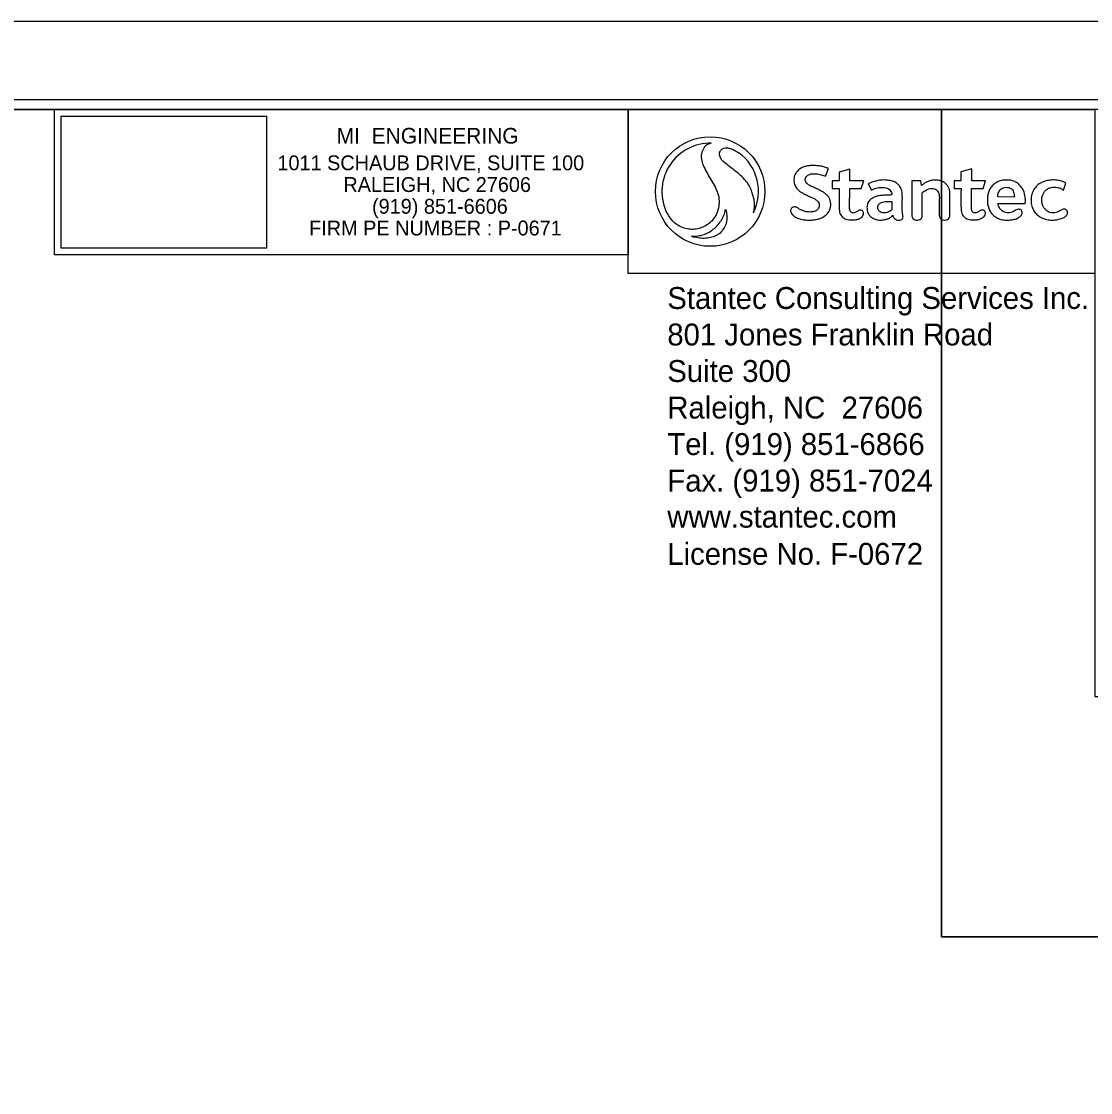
# Model space of a CAD drawing. Extents: x 2568837 to 2570520, y 536545 to 537640.
# Drawn here: x 2570028.8 to 2570302.1, y 537365.9 to 537639.6 of the extents above; entities that cross this region are included whole.
import ezdxf

# ---------------------------------------------------------------- set-up
doc = ezdxf.new("R2010")
doc.units = 0
for name, color, linetype in [('Old_Level_1', 7, 'Continuous'), ('Prop DSN Text', 7, 'Continuous'), ('Prop Grid Mask', 7, 'Continuous'), ('Scratch_Level_0', 7, 'Continuous'), ('Sheet Clip Boundary CELL', 7, 'Continuous'), ('Sheet Cutting Line CELL', 7, 'Continuous'), ('Sheet Data Text CELL', 7, 'Continuous'), ('Sheet Layout Plan Border', 7, 'Continuous'), ('Sheet North Arrow Point CELL', 7, 'Continuous'), ('Sheet Plan CELL', 7, 'Continuous'), ('Sheet Plan Layout CELL', 7, 'Continuous'), ('Sheet Plot Border Inside CELL', 7, 'Continuous'), ('Sheet Plot Border Outside CELL', 7, 'Continuous')]:
    doc.layers.add(name, color=color, linetype=linetype)

msp = doc.modelspace()

# ---------------------------------------------------------------- linework, layer by layer
at = {"layer": 'Old_Level_1'}
msp.add_lwpolyline([(2570037.18, 537617.15), (2570183.85, 537617.15), (2570183.85, 537579.97), (2570037.18, 537579.97)], close=True, dxfattribs=at)
at = {"layer": 'Prop DSN Text'}
msp.add_lwpolyline([(2570038.8, 537581.75), (2570091.47, 537581.75), (2570091.47, 537615.37), (2570038.8, 537615.37)], close=True, dxfattribs=at)
at = {"layer": 'Scratch_Level_0'}
msp.add_lwpolyline([(2570183.85, 537617.15), (2570303.14, 537617.16), (2570303.15, 537575.21), (2570183.85, 537575.19)], close=True, dxfattribs=at)
at = {"layer": 'Sheet Clip Boundary CELL'}
msp.add_lwpolyline([(2569053.18, 536567.15), (2570453.19, 536567.15), (2570453.19, 537405.66), (2570263.93, 537405.66), (2570263.93, 537617.15), (2569053.18, 537617.15)], close=True, dxfattribs=at)
at = {"layer": 'Sheet Cutting Line CELL'}
msp.add_line((2570520.19, 537639.64), (2568836.69, 537639.64), dxfattribs=at)
at = {"layer": 'Sheet Data Text CELL'}
for p, q in [((2570234.35, 537600.09), (2570235.04, 537602.04)), ((2570240.54, 537601.92), (2570237.78, 537601.15)), ((2570240.54, 537598.86), (2570240.54, 537601.92)), ((2570271.69, 537601.93), (2570268.93, 537601.16)), ((2570271.69, 537598.86), (2570271.69, 537601.93)), ((2570237.78, 537598.86), (2570236.03, 537598.86)), ((2570236.03, 537598.86), (2570236.03, 537596.94)), ((2570237.78, 537601.15), (2570237.78, 537598.86)), ((2570244.1, 537598.86), (2570240.54, 537598.86)), ((2570243.44, 537596.94), (2570244.1, 537598.86)), ((2570258.66, 537598.86), (2570256.34, 537598.86)), ((2570256.34, 537598.86), (2570256.35, 537590.06)), ((2570258.82, 537597.69), (2570258.66, 537598.86)), ((2570268.93, 537598.87), (2570267.18, 537598.87)), ((2570267.18, 537598.87), (2570267.18, 537596.95)), ((2570268.93, 537601.16), (2570268.93, 537598.87)), ((2570275.25, 537598.86), (2570271.69, 537598.86)), ((2570274.59, 537596.95), (2570275.25, 537598.86)), ((2570236.03, 537596.94), (2570237.8, 537596.94)), ((2570240.48, 537592.1), (2570240.52, 537596.94)), ((2570240.52, 537596.94), (2570243.44, 537596.94)), ((2570245.25, 537598.16), (2570246.09, 537596.54)), ((2570259.04, 537590.07), (2570259.04, 537595.87)), ((2570267.18, 537596.95), (2570268.95, 537596.95)), ((2570271.63, 537592.1), (2570271.67, 537596.95)), ((2570271.67, 537596.95), (2570274.59, 537596.95)), ((2570295.14, 537596.48), (2570295.75, 537598.28)), ((2570251.28, 537593.65), (2570251.28, 537591.48)), ((2570282.59, 537594.76), (2570278.39, 537594.77)), ((2570278.39, 537593.08), (2570285.38, 537593.08))]:
    msp.add_line(p, q, dxfattribs=at)
for points in [[(2570205.09, 537608.51), (2570205.09, 537608.51)], [(2570212.18, 537606.09), (2570212.18, 537606.09)]]:
    msp.add_lwpolyline(points, dxfattribs=at)
msp.add_circle((2570204.83, 537596.17), 14, dxfattribs=at)
for start, end in [(88.7738, 203.6916), (88.7673, 88.7738), (333.7886, 53.4398), (247.1256, 251.4651)]:
    msp.add_arc((2570204.83, 537596.17), 12.34, start, end, dxfattribs=at)
for points, degree in [([(2570205.09, 537608.51), (2570204.79, 537608.45), (2570204.09, 537608.3), (2570203.17, 537607.37), (2570202.49, 537605.83), (2570202.58, 537604.11), (2570203.19, 537602.44), (2570204.11, 537600.83), (2570205.07, 537599.04), (2570206.12, 537597.35), (2570206.86, 537595.64), (2570207.2, 537593.78), (2570206.98, 537591.91), (2570206.43, 537590.2), (2570205.38, 537588.64), (2570204, 537587.54), (2570202.55, 537586.89), (2570201.24, 537586.48), (2570199.78, 537586.48), (2570198.16, 537586.71), (2570196.55, 537587.44), (2570194.84, 537588.89), (2570194.03, 537590.31), (2570193.52, 537591.21)], 3), ([(2570205.09, 537608.51), (2570205.09, 537608.51), (2570205.09, 537608.51), (2570205.09, 537608.51)], 2), ([(2570215.9, 537590.72), (2570216.01, 537591.15), (2570216.19, 537591.97), (2570216.16, 537593.27), (2570216.03, 537594.42), (2570215.69, 537595.48), (2570215.3, 537596.71), (2570214.6, 537598.05), (2570213.6, 537599.31), (2570212.31, 537600.63), (2570210.68, 537601.81), (2570209.01, 537603.18), (2570207.67, 537604.18), (2570207.2, 537605.37), (2570207.19, 537606.27), (2570207.64, 537606.88), (2570208.23, 537607.3), (2570209.02, 537607.37), (2570209.95, 537607.19), (2570211.03, 537606.74), (2570211.78, 537606.32), (2570212.18, 537606.09)], 3), ([(2570235.04, 537602.04), (2570234.91, 537602.1), (2570234.37, 537602.36), (2570233.33, 537602.63), (2570232.06, 537602.79), (2570230.9, 537602.85), (2570229.93, 537602.75), (2570229.01, 537602.56), (2570228.12, 537602.21), (2570227.26, 537601.62), (2570226.64, 537600.83), (2570226.29, 537600.03), (2570226.21, 537599.29), (2570226.25, 537598.6), (2570226.39, 537597.95), (2570226.67, 537597.41), (2570227.01, 537596.92), (2570227.42, 537596.48), (2570227.93, 537596.08), (2570228.55, 537595.7), (2570229.31, 537595.31), (2570230.16, 537594.92), (2570231.03, 537594.55), (2570231.74, 537594.18), (2570232.27, 537593.74), (2570232.63, 537593.32), (2570232.75, 537592.8), (2570232.74, 537592.32), (2570232.54, 537591.78), (2570232.09, 537591.33), (2570231.38, 537591.03), (2570230.54, 537590.91), (2570229.61, 537590.95), (2570228.79, 537591.12), (2570228.13, 537591.45), (2570227.59, 537591.67), (2570227.22, 537592.01), (2570226.88, 537592.14), (2570226.56, 537592.28), (2570226.22, 537592.25), (2570225.88, 537592.15), (2570225.59, 537591.9), (2570225.4, 537591.54), (2570225.39, 537591.15), (2570225.45, 537590.76), (2570225.75, 537590.35), (2570226.34, 537589.77), (2570227.38, 537589.26), (2570228.66, 537588.92), (2570229.96, 537588.85), (2570231.09, 537588.88), (2570232.06, 537589.01), (2570232.92, 537589.27), (2570233.82, 537589.67), (2570234.68, 537590.35), (2570235.35, 537591.19), (2570235.62, 537592.17), (2570235.66, 537593.07), (2570235.55, 537593.88), (2570235.24, 537594.52), (2570234.85, 537595.17), (2570234.18, 537595.72), (2570233.42, 537596.23), (2570232.58, 537596.63), (2570231.68, 537597.06), (2570230.73, 537597.46), (2570229.93, 537597.89), (2570229.39, 537598.37), (2570229.16, 537598.85), (2570229.12, 537599.35), (2570229.27, 537599.8), (2570229.57, 537600.2), (2570230, 537600.48), (2570230.57, 537600.69), (2570231.25, 537600.74), (2570231.92, 537600.71), (2570232.58, 537600.61), (2570233.22, 537600.47), (2570233.83, 537600.29), (2570234.19, 537600.15), (2570234.35, 537600.09)], 3), ([(2570251.54, 537590.11), (2570251.55, 537590.02), (2570251.57, 537589.79), (2570251.8, 537589.46), (2570252.12, 537589.08), (2570252.71, 537588.81), (2570253.33, 537588.83), (2570253.9, 537588.96), (2570254.13, 537589.41), (2570254.14, 537589.87), (2570254.01, 537590.48), (2570253.86, 537592.17), (2570253.97, 537593.95), (2570253.94, 537595.87), (2570253.72, 537596.81), (2570253.19, 537597.65), (2570252.63, 537598.29), (2570251.7, 537598.76), (2570250.55, 537599.06), (2570249.18, 537599.15), (2570247.8, 537599.01), (2570246.46, 537598.7), (2570245.64, 537598.34), (2570245.25, 537598.16)], 3), ([(2570259.04, 537595.87), (2570259.09, 537595.91), (2570259.28, 537596.08), (2570259.73, 537596.36), (2570260.31, 537596.74), (2570261.06, 537596.97), (2570261.81, 537596.96), (2570262.54, 537596.73), (2570263.04, 537596.21), (2570263.31, 537595.59), (2570263.45, 537594.75), (2570263.36, 537593.5), (2570263.43, 537591.91), (2570263.34, 537590.59), (2570263.4, 537589.68), (2570263.71, 537589.19), (2570264.26, 537588.84), (2570264.9, 537588.85), (2570265.51, 537589), (2570266.01, 537589.37), (2570266.15, 537590.1), (2570266.04, 537591.38), (2570266.11, 537592.95), (2570266.08, 537594.68), (2570266.14, 537595.77), (2570265.99, 537596.73), (2570265.69, 537597.4), (2570265.22, 537598.09), (2570264.45, 537598.62), (2570263.49, 537599.08), (2570262.39, 537599.11), (2570261.4, 537599.05), (2570260.51, 537598.76), (2570259.72, 537598.39), (2570259.19, 537597.97), (2570258.91, 537597.76), (2570258.82, 537597.69)], 3), ([(2570285.38, 537593.08), (2570285.39, 537593.34), (2570285.42, 537594.02), (2570285.3, 537595.09), (2570285.02, 537596.3), (2570284.44, 537597.23), (2570283.79, 537598.05), (2570282.95, 537598.62), (2570281.9, 537599.03), (2570280.71, 537599.11), (2570279.55, 537599.09), (2570278.44, 537598.74), (2570277.5, 537598.2), (2570276.67, 537597.42), (2570276.11, 537596.46), (2570275.8, 537595.42), (2570275.68, 537594.36), (2570275.66, 537593.22), (2570275.92, 537592.16), (2570276.34, 537591.12), (2570276.98, 537590.24), (2570277.95, 537589.54), (2570279.16, 537588.94), (2570280.57, 537588.86), (2570281.85, 537588.88), (2570282.94, 537589.11), (2570283.8, 537589.53), (2570284.43, 537590.07), (2570284.65, 537590.66), (2570284.55, 537591.14), (2570284.32, 537591.52), (2570283.94, 537591.62), (2570283.57, 537591.67), (2570283.14, 537591.54), (2570282.63, 537591.22), (2570282.05, 537590.87), (2570281.34, 537590.71), (2570280.68, 537590.69), (2570280.03, 537590.86), (2570279.49, 537591.23), (2570278.95, 537591.66), (2570278.64, 537592.25), (2570278.44, 537592.72), (2570278.4, 537592.99), (2570278.39, 537593.08)], 3), ([(2570295.75, 537598.28), (2570295.52, 537598.41), (2570294.95, 537598.74), (2570293.83, 537599.03), (2570292.43, 537599.17), (2570290.95, 537599), (2570289.54, 537598.54), (2570288.37, 537597.76), (2570287.52, 537596.7), (2570287, 537595.47), (2570286.81, 537594.1), (2570286.92, 537592.71), (2570287.39, 537591.47), (2570288.1, 537590.51), (2570289.07, 537589.68), (2570290.41, 537589.06), (2570291.97, 537588.81), (2570293.41, 537588.91), (2570294.6, 537589.22), (2570295.54, 537589.65), (2570296.15, 537590.24), (2570296.18, 537590.8), (2570296.13, 537591.22), (2570295.85, 537591.48), (2570295.56, 537591.65), (2570295.24, 537591.67), (2570294.81, 537591.6), (2570294.42, 537591.27), (2570293.87, 537591.03), (2570293.31, 537590.77), (2570292.51, 537590.71), (2570291.68, 537590.78), (2570290.87, 537591.22), (2570290.27, 537591.82), (2570289.79, 537592.55), (2570289.64, 537593.41), (2570289.52, 537594.26), (2570289.76, 537595.1), (2570290.08, 537595.86), (2570290.56, 537596.48), (2570291.2, 537596.93), (2570291.94, 537597.22), (2570292.8, 537597.29), (2570293.66, 537597.21), (2570294.48, 537596.95), (2570294.93, 537596.63), (2570295.14, 537596.48)], 3), ([(2570237.8, 537596.94), (2570237.79, 537595.23), (2570237.78, 537593.42), (2570237.8, 537591.41), (2570237.89, 537590.92), (2570238.09, 537590.26), (2570238.46, 537589.82), (2570238.84, 537589.46), (2570239.24, 537589.2), (2570239.88, 537588.97), (2570240.76, 537588.88), (2570241.67, 537588.92), (2570242.58, 537589.04), (2570243.27, 537589.39), (2570243.78, 537589.81), (2570244.02, 537590.28), (2570244.04, 537590.69), (2570243.97, 537591.04), (2570243.79, 537591.24), (2570243.57, 537591.37), (2570243.31, 537591.42), (2570243.04, 537591.43), (2570242.76, 537591.36), (2570242.51, 537591.16), (2570242.24, 537590.95), (2570241.89, 537590.8), (2570241.53, 537590.68), (2570241.16, 537590.73), (2570240.83, 537590.9), (2570240.58, 537591.16), (2570240.47, 537591.59), (2570240.48, 537591.9), (2570240.48, 537592.1)], 3), ([(2570246.09, 537596.54), (2570246.22, 537596.6), (2570246.6, 537596.81), (2570247.23, 537597), (2570247.98, 537597.19), (2570248.69, 537597.24), (2570249.43, 537597.21), (2570250.1, 537597.01), (2570250.68, 537596.67), (2570251.09, 537596.18), (2570251.27, 537595.69), (2570251.27, 537595.38), (2570251.27, 537595.28)], 3), ([(2570268.95, 537596.95), (2570268.94, 537595.23), (2570268.93, 537593.43), (2570268.95, 537591.41), (2570269.04, 537590.93), (2570269.24, 537590.27), (2570269.61, 537589.82), (2570269.99, 537589.47), (2570270.39, 537589.2), (2570271.03, 537588.98), (2570271.91, 537588.88), (2570272.82, 537588.92), (2570273.73, 537589.05), (2570274.42, 537589.4), (2570274.93, 537589.81), (2570275.17, 537590.28), (2570275.19, 537590.69), (2570275.12, 537591.04), (2570274.94, 537591.25), (2570274.72, 537591.38), (2570274.46, 537591.42), (2570274.19, 537591.43), (2570273.91, 537591.36), (2570273.66, 537591.16), (2570273.39, 537590.95), (2570273.04, 537590.8), (2570272.68, 537590.69), (2570272.31, 537590.73), (2570271.98, 537590.91), (2570271.73, 537591.16), (2570271.62, 537591.59), (2570271.63, 537591.9), (2570271.63, 537592.1)], 3), ([(2570278.39, 537594.77), (2570278.39, 537594.85), (2570278.39, 537595.07), (2570278.41, 537595.48), (2570278.55, 537596), (2570278.88, 537596.56), (2570279.39, 537597.01), (2570280.08, 537597.25), (2570280.83, 537597.27), (2570281.53, 537597.06), (2570282.12, 537596.68), (2570282.41, 537596.03), (2570282.56, 537595.39), (2570282.58, 537594.96), (2570282.59, 537594.76)], 3), ([(2570251.27, 537595.28), (2570251.09, 537595.27), (2570250.51, 537595.26), (2570249.51, 537595.21), (2570248.33, 537595.15), (2570247.21, 537594.91), (2570246.19, 537594.48), (2570245.29, 537593.71), (2570244.87, 537592.62), (2570244.93, 537591.6), (2570245.09, 537590.71), (2570245.63, 537589.97), (2570246.41, 537589.29), (2570247.52, 537588.88), (2570248.67, 537588.86), (2570249.74, 537589), (2570250.55, 537589.28), (2570251.15, 537589.7), (2570251.4, 537589.96), (2570251.54, 537590.11)], 3), ([(2570251.28, 537591.48), (2570251.21, 537591.42), (2570250.95, 537591.23), (2570250.48, 537590.97), (2570249.83, 537590.71), (2570249.14, 537590.66), (2570248.54, 537590.82), (2570248.11, 537591.09), (2570247.84, 537591.41), (2570247.66, 537591.8), (2570247.63, 537592.21), (2570247.71, 537592.63), (2570247.96, 537593.02), (2570248.38, 537593.27), (2570248.89, 537593.5), (2570249.55, 537593.59), (2570250.23, 537593.62), (2570250.83, 537593.66), (2570251.15, 537593.66), (2570251.28, 537593.65)], 3), ([(2570200.03, 537584.8), (2570200.33, 537584.77), (2570201.04, 537584.7), (2570202.27, 537584.94), (2570203.63, 537585.26), (2570204.86, 537585.97), (2570206, 537586.77), (2570207.06, 537587.91), (2570207.94, 537589.18), (2570208.5, 537590.5), (2570208.67, 537591.28), (2570208.75, 537591.66)], 3), ([(2570208.75, 537591.66), (2570208.84, 537591.34), (2570209.07, 537590.54), (2570209.13, 537589.2), (2570208.9, 537587.75), (2570208.15, 537586.43), (2570207.14, 537585.21), (2570205.68, 537584.54), (2570204.12, 537584.19), (2570202.52, 537584.16), (2570201.42, 537584.37), (2570200.9, 537584.47)], 3), ([(2570256.35, 537590.06), (2570256.37, 537589.95), (2570256.43, 537589.69), (2570256.62, 537589.24), (2570257.11, 537588.87), (2570257.8, 537588.86), (2570258.49, 537588.91), (2570258.9, 537589.37), (2570259.05, 537589.76), (2570259.05, 537589.97), (2570259.04, 537590.07)], 3)]:
    msp.add_open_spline(points, degree=degree, dxfattribs=at)
at = {"layer": 'Sheet Layout Plan Border'}
msp.add_lwpolyline([(2569053.18, 536567.15), (2570453.19, 536567.15), (2570453.19, 537405.66), (2570263.93, 537405.66), (2570263.93, 537617.15), (2569053.18, 537617.15)], close=True, dxfattribs=at)
at = {"layer": 'Sheet North Arrow Point CELL'}
msp.add_line((2570235.07, 537544.21), (2570235.07, 537544.21), dxfattribs=at)
at = {"layer": 'Sheet Plan CELL'}
for points in [[(2569003.18, 536567.15), (2569003.15, 537617.13), (2570303.14, 537617.16), (2570303.15, 537467.1), (2570503.19, 537467.09), (2570503.19, 536567.15)], [(2570503.22, 537617.15), (2569003.18, 537617.15), (2569003.18, 536567.15), (2570503.19, 536567.15)]]:
    msp.add_lwpolyline(points, close=True, dxfattribs=at)
at = {"layer": 'Sheet Plan Layout CELL'}
for points in [[(2569003.15, 537617.13), (2569003.18, 536567.15), (2570503.18, 536567.15), (2570503.18, 537405.66), (2570263.93, 537405.66), (2570263.93, 537617.15)], [(2570263.93, 537405.66), (2570503.2, 537405.66), (2570503.23, 537617.15), (2570263.93, 537617.15)]]:
    msp.add_lwpolyline(points, close=True, dxfattribs=at)
at = {"layer": 'Sheet Plot Border Inside CELL'}
msp.add_lwpolyline([(2568849.69, 536564.64), (2570515.68, 536564.65), (2570515.69, 537619.64), (2568849.69, 537619.64)], close=True, dxfattribs=at)
at = {"layer": 'Sheet Plot Border Outside CELL'}
msp.add_lwpolyline([(2568836.69, 536544.64), (2570520.19, 536544.64), (2570520.19, 537639.64), (2568836.69, 537639.64)], close=True, dxfattribs=at)

# ---------------------------------------------------------------- texts
at = {"layer": 'Prop Grid Mask'}
for s, height, rotation, p in [('MI  ENGINEERING', 4.0137, 360, (2570109.35, 537608.41)), ('1011 SCHAUB DRIVE, SUITE 100', 3.7957, 359.9996, (2570094.2, 537601.6)), ('RALEIGH, NC 27606', 3.7957, 359.9998, (2570111.06, 537596.05)), ('(919) 851-6606', 3.7957, 359.9998, (2570118.39, 537590.49)), ('FIRM PE NUMBER : P-0671', 3.7957, 359.9998, (2570102.3, 537584.94))]:
    msp.add_text(s, height=height, rotation=rotation, dxfattribs=at).set_placement(p)
at = {"layer": 'Sheet Data Text CELL'}
for s, height, p in [('Stantec Consulting Services Inc.', 5.6014, (2570193.87, 537566.15)), ('801 Jones Franklin Road', 5.6014, (2570193.87, 537556.82)), ('Suite 300', 5.601, (2570193.87, 537547.49)), ('Raleigh, NC  27606', 5.6014, (2570193.87, 537538.15)), ('Tel. (919) 851-6866', 5.6014, (2570193.87, 537528.82)), ('Fax. (919) 851-7024', 5.6014, (2570193.87, 537519.49)), ('www.stantec.com', 5.6014, (2570193.87, 537510.27)), ('License No. F-0672', 5.6014, (2570193.87, 537500.76))]:
    msp.add_text(s, height=height, rotation=0.0071, dxfattribs=at).set_placement(p)

doc.saveas('drawing.dxf')
